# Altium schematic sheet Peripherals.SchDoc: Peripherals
size A4; Project: STM32MP15-DISCO PI; Date: Not used; ApprovedBy: Not used; CheckedBy: Not used; Author: Not used; CompanyName: STMicroelectronics; DrawnBy: Not used; Engineer: Not used; Organization: Not used; Address1: Not used; Address2: Not used; Address3: Not used; Address4: Not used; DocumentNumber: 13; Revision: Not used; SheetNumber: 13; SheetTotal: 15
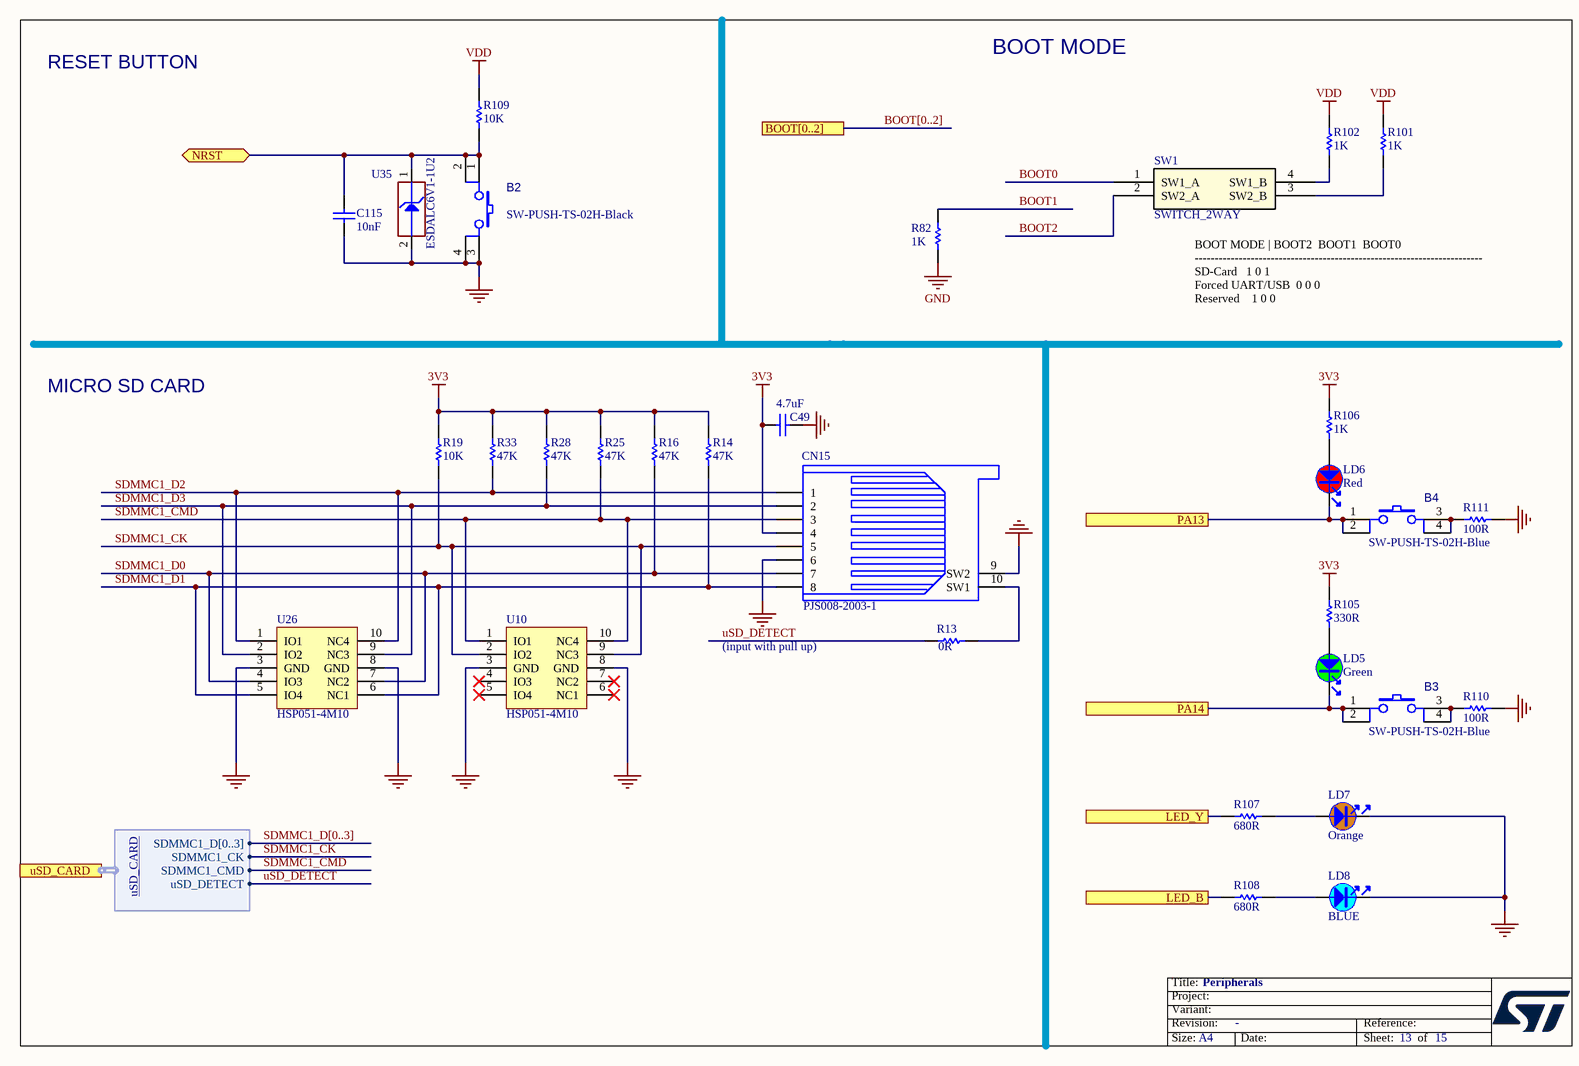
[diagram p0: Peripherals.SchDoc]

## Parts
B2  value SW-PUSH-TS-02H-Black  [SWI_JIUBABA_C-TS-02H-2-5-K-V-T_R_BLACK]
B3  SW-PUSH-TS-02H-Blue  [SWI_JIUBABA_C-TS-02H-2-5-B-V-T_R_BLUE]
B4  SW-PUSH-TS-02H-Blue  [SWI_JIUBABA_C-TS-02H-2-5-B-V-T_R_BLUE]
C49  value 4.7uF  [C0402]  (hidden comment: Capacitor)
C115  value 10nF  [C0402]  (hidden comment: Capacitor)
CN15  value PJS008-2003-1  [CON_MICROSD_YAMAICHI_PJS008-2003-0]
LD5  value Green  [LED_0603_GREEN]  (hidden comment: LED_green)
LD6  value Red  [LED_0603_RED]  (hidden comment: LED_red)
LD7  value Orange  [LED_0603_ORANGE_H0P4]  (hidden comment: LED_orange)
LD8  value BLUE  [LED_0603_SMD-B_BLUE_H0P4]  (hidden comment: LED_blue)
R13  value 0R  [R0402]
R14  value 47K  [R0402]
R16  value 47K  [R0402]
R19  value 10K  [R0402]
R25  value 47K  [R0402]
R28  value 47K  [R0402]
R33  value 47K  [R0402]
R82  value 1K  [R0402]  (hidden comment: Resistor)
R101  value 1K  [R0402]
R102  value 1K  [R0402]
R105  value 330R  [R0402]
R106  value 1K  [R0402]
R107  value 680R  [R0402]  (hidden comment: Resistor)
R108  value 680R  [R0402]  (hidden comment: Resistor)
R109  value 10K  [R0402]
R110  value 100R  [R0402]
R111  value 100R  [R0402]
SW1  SWITCH_2WAY  [SWI_C&K_SDA02H1SBD_2POS]
U10  HSP051-4M10  [ESD_UQFN-10L_2P5X1_P050]
U26  HSP051-4M10  [ESD_UQFN-10L_2P5X1_P050]
U35  value ESDALC6V1-1U2  [ESD_ST0201]  (hidden comment: ESD-TRANSIL)

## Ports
BOOT[0..2], LED_B, LED_Y, NRST (bidir), PA13, PA14, uSD_CARD (harness uSD_CARD)

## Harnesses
uSD_CARD: SDMMC1_D[0..3], SDMMC1_CK, SDMMC1_CMD, uSD_DETECT

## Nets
3V3: C49.2 CN15.4 R14.2 R16.2 R19.2 R25.2 R28.2 R33.2 R105.2 R106.2
GND: B2.3 B2.4 C49.1 C115.1 CN15.6 CN15.9(SW2) LD7.2 LD8.2 R82.1 R110.2 R111.2 U10.3(GND) U10.8(GND) U26.3(GND) U26.8(GND) U35.2(GND)
VDD: R101.2 R102.2 R109.2
BOOT0: SW1.1(SW1_A)
BOOT1: R82.2
BOOT2: SW1.2(SW2_A)
LED_B: R108.1 ; port LED_B
LED_Y: R107.1 ; port LED_Y
NRST: B2.1 B2.2 C115.2 R109.1 U35.1(IO1) ; port NRST
PA13: B4.1 B4.2 LD6.2 ; port PA13
PA14: B3.1 B3.2 LD5.2 ; port PA14
SDMMC1_CK: CN15.5 R19.1 U10.2(IO2) U10.9(NC3) ; port uSD_CARD.SDMMC1_CK
SDMMC1_CMD: CN15.3 R25.1 U10.1(IO1) U10.10(NC4) ; port uSD_CARD.SDMMC1_CMD
SDMMC1_D0: CN15.7 R16.1 U26.4(IO3) U26.7(NC2)
SDMMC1_D1: CN15.8 R14.1 U26.5(IO4) U26.6(NC1)
SDMMC1_D2: CN15.1 R33.1 U26.1(IO1) U26.10(NC4)
SDMMC1_D3: CN15.2 R28.1 U26.2(IO2) U26.9(NC3)
uSD_DETECT: R13.1 ; port uSD_CARD.uSD_DETECT
NetB3_3: B3.3 B3.4 R110.1
NetB4_3: B4.3 B4.4 R111.1
NetCN15_10: CN15.10(SW1) R13.2
NetLD5_1: LD5.1 R105.1
NetLD6_1: LD6.1 R106.1
NetLD7_1: LD7.1 R107.2
NetLD8_1: LD8.1 R108.2
NetR101_1: R101.1 SW1.3(SW2_B)
NetR102_1: R102.1 SW1.4(SW1_B)

Not connected (* = marked no-connect by the designer): U10 4(IO3)* 5(IO4)* 6(NC1)* 7(NC2)*

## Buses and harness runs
bus BOOT[0..2] = port BOOT[0..2]
bus SDMMC1_D[0..3]

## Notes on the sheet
- BOOT MODE
- RESET BUTTON
- (near SW1) BOOT MODE	|	BOOT2 	BOOT1 	BOOT0
  ------------------------------------------------------------------------
  SD-Card			1	0	1
  Forced UART/USB		0	0	0
  Reserved 			1	0	0
- MICRO SD CARD
- (input with pull up)

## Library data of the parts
B2 = MCD-00171: Switch HW SMD black; Manufacturer_Part_Number: C-TS-02H-2.5-K-V-T/R BLACK; Manufacturer: JIUBABA; Part_Type: Misc; Provided_By: SUBCO; Initial_Board_Reference: MB1264
B3 B4 = MCD-00172: Switch HW SMD blue; Part_Type: Misc; Manufacturer_Part_Number: C-TS-02H-2.5-B-V-T/R BLUE; Manufacturer: JIUBABA; Provided_By: SUBCO; Initial_Board_Reference: MB1264
C49 = MCD-01356: Capacitor, MLCC, 4.7uF, 6V3, X5R, 20%, 0402, T=0,5mm; Manufacturer_Part_Number: GRM155R60J475ME47; Manufacturer: MURATA; Provided_By: SUBCO
C115 = MCD-00011: Capacitor, MLCC, 10nF, 16V, X7R, 10%, 0402, T=0.5mm; Manufacturer_Part_Number: CC0402KRX7R7BB103; Manufacturer: YAGEO; Provided_By: SUBCO; Initial_Board_Reference: MB1274
CN15 = MCD-00023: MicroSD Card Conn, Reversed-Type, Mnt Push-Push; Manufacturer: YAMAICHI; Part_Type: Connector; Provided_By: SUBCO; Initial_Board_Reference: mb1274
LD5 = MCD-02900: LED, Green, 2V, 20mA, 0603; Part_Type: Display; Part_Preference: Recommended; Manufacturer: EVERLIGHT; Manufacturer_Part_Number: 19-213SYGC/S530-E2/5T; Full_Alternate_Internal_Part_Number: MCD-00320; Partial_Alternate_Internal_Part_Number: MCD-00050; Component_Country_Of_Origin: China; ShowFields: YES; ID: 5016
LD6 = MCD-02899: LED, Red, 2V35, 20mA, 0603; Part_Type: Display; Part_Preference: Recommended; Manufacturer: EVERLIGHT; Manufacturer_Part_Number: 19-213/R6C-AP1Q2B/5T; Full_Alternate_Internal_Part_Number: MCD-00049; Component_Country_Of_Origin: China; ShowFields: YES; ID: 5015
LD7 = MCD-02785: LED, Orange, 2V2, 5mA, 0603; Part_Type: Display; Part_Preference: Recommended; Manufacturer: EVERLIGHT; Manufacturer_Part_Number: 19-217/S2C-AM2N2VY/6T; Full_Alternate_Internal_Part_Number: MCD-00321; Component_Country_Of_Origin: China; ShowFields: YES; ID: 4897
LD8 = MCD-02786: LED, Blue, VF: Min=2.5V, Max=3.1V, 10mA, 0603; Part_Type: Display; Part_Preference: Recommended; Manufacturer: EVERLIGHT; Manufacturer_Part_Number: 19-217/BHC-ZL1M2RY/6T; Full_Alternate_Internal_Part_Number: MCD-01131; Component_Country_Of_Origin: China; ShowFields: YES; ID: 4898
R13 = MCD-00052: Resistor,0R,0402,5%,1/16W; Manufacturer_Part_Number: RC0402JR-070RL; Manufacturer: YAGEO; Provided_By: SUBCO; Initial_Board_Reference: mb1274
R14 R16 R25 R28 R33 = MCD-00063: Resistor,47K,0402,1%,1/16W; Manufacturer_Part_Number: RC0402FR-0747KL; Manufacturer: YAGEO; Provided_By: SUBCO; Initial_Board_Reference: mb1274
R19 R109 = MCD-00053: Resistor,10K,0402,1%,1/16W; Manufacturer_Part_Number: RC0402FR-0710KL; Manufacturer: YAGEO; Provided_By: SUBCO; Initial_Board_Reference: mb1274
R82 = MCD-00061: Resistor,1K,0402,1%,1/16W; Manufacturer_Part_Number: RC0402FR-071KL; Manufacturer: YAGEO; Provided_By: SUBCO; Initial_Board_Reference: MB1274
R101 R102 R106 = MCD-00061: Resistor,1K,0402,1%,1/16W; Manufacturer_Part_Number: RC0402FR-071KL; Manufacturer: YAGEO; Provided_By: SUBCO; Initial_Board_Reference: mb1274
R105 = MCD-00062: Resistor,330R,0402,1%,1/16W; Manufacturer_Part_Number: RC0402FR-07330RL; Manufacturer: YAGEO; Provided_By: SUBCO; Initial_Board_Reference: mb1274
R107 R108 = MCD-00507: Resistor,680R,0402,1%,1/16W; Manufacturer_Part_Number: RC0402FR-07680RL; Manufacturer: YAGEO; Provided_By: SUBCO
R110 R111 = MCD-00067: Resistor,100R,0402,1%,1/16W; Manufacturer_Part_Number: RC0402FR-07100RL; Manufacturer: YAGEO; Provided_By: SUBCO; Initial_Board_Reference: mb1274
SW1 = MCD-00658: Dip Switch ,2Position ,Surface Mount Slide (Standard) ,2.54 pitch,25mA 24VDC; Part_Type: Misc; Manufacturer_Part_Number: SDA02H1SBD; Manufacturer: C&K; Provided_By: SUBCO; Initial_Board_Reference: MB1272
U10 U26 = MCD-00667: 4-line ESD protection for high speed lines; Part_Type: Diode; Manufacturer: STMICROELECTRONICS; BMS_Part_Number: 9179041; ECCN_US: EAR99; ECCN_EU: NEC; Provided_By: SUBCO with ST control; Initial_Board_Reference: MB1331
U35 = MCD-00170: ESD protection 6V1; Part_Type: Diode; Manufacturer: STMICROELECTRONICS; BMS_Part_Number: 9151132; ECCN_US: EAR99; ECCN_EU: NEC; Provided_By: SUBCO with ST control; Initial_Board_Reference: MB1274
